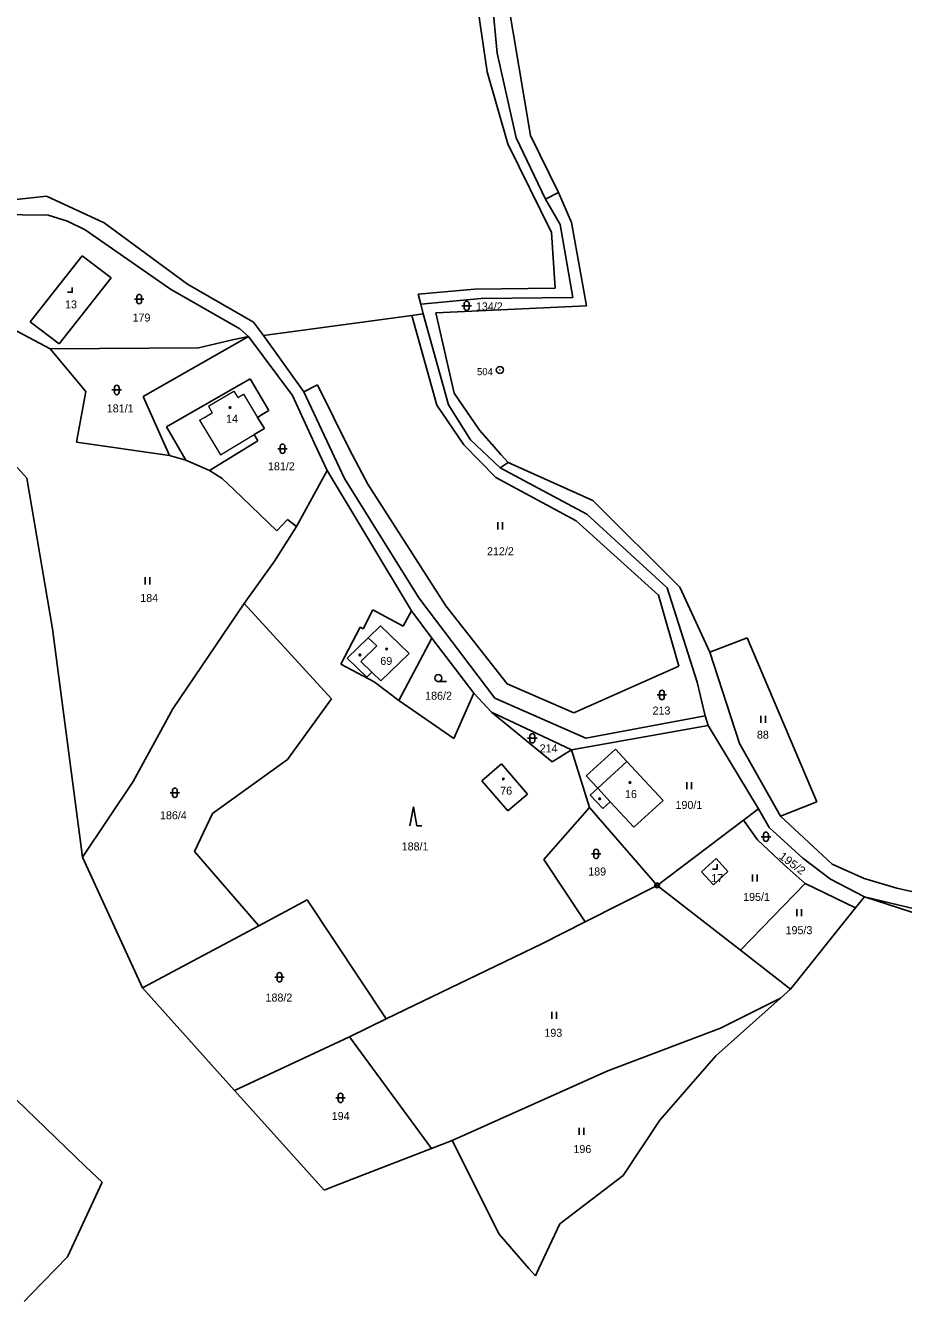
# Model space of a CAD drawing. Extents: x -744132 to -742433, y -984679 to -982287.
# Drawn here: x -742991 to -742804.5, y -984511 to -984240 of the extents above; entities that cross this region are included whole.
import ezdxf
from ezdxf.enums import TextEntityAlignment as Align

# ---------------------------------------------------------------- set-up
doc = ezdxf.new("R2010")
doc.units = 0
doc.header["$LTSCALE"] = 0.68
for name, color, linetype, lineweight in [('1', 7, 'Continuous', 25), ('3', 7, 'Continuous', 25), ('4', 7, 'Continuous', 13), ('5', 7, 'Continuous', 25), ('8', 7, 'Continuous', 25)]:
    doc.layers.add(name, color=color, linetype=linetype, lineweight=lineweight)
doc.layers.add('2', color=7, linetype='Continuous')

msp = doc.modelspace()

# ---------------------------------------------------------------- linework, layer by layer
at = {"layer": '1'}
for p, q in [((-742892.96, -984249.85), (-742897.56, -984218.2)), ((-742893.47, -984218.33), (-742890.83, -984245.87)), ((-742890.85, -984221.06), (-742883.73, -984263.4)), ((-742890.83, -984245.87), (-742886.76, -984263.88)), ((-742888.54, -984265.18), (-742892.96, -984249.85)), ((-742879.29, -984283.96), (-742888.54, -984265.18)), ((-742886.76, -984263.88), (-742880.58, -984276.92)), ((-742996.15, -984277.35), (-742986.54, -984276.26)), ((-742986.54, -984276.26), (-742974.27, -984281.97)), ((-742880.58, -984276.92), (-742877.81, -984275.46)), ((-742880.58, -984276.92), (-742877.42, -984282.31)), ((-742998.92, -984280.13), (-742986.17, -984280.32)), ((-742986.17, -984280.32), (-742982.09, -984281.55)), ((-742982.09, -984281.55), (-742978.35, -984283.42)), ((-742978.35, -984283.42), (-742960.2, -984296.05)), ((-742974.27, -984281.97), (-742956.59, -984294.93)), ((-742878.5, -984295.83), (-742879.29, -984283.96)), ((-742877.42, -984282.31), (-742874.73, -984297.82)), ((-742874.99, -984281.86), (-742871.87, -984299.55)), ((-742978.94, -984288.95), (-742990, -984302.96)), ((-742978.94, -984288.95), (-742972.79, -984293.61)), ((-742972.79, -984293.61), (-742983.86, -984307.62)), ((-742956.59, -984294.93), (-742942.55, -984303.04)), ((-742960.2, -984296.05), (-742945.46, -984304.44)), ((-742907.61, -984297.1), (-742895.64, -984296.05)), ((-742907.03, -984299.2), (-742907.61, -984297.1)), ((-742895.64, -984296.05), (-742878.5, -984295.83)), ((-742874.73, -984297.82), (-742894.23, -984297.98)), ((-743003.32, -984299.32), (-742985.75, -984308.73)), ((-742894.23, -984297.98), (-742907.03, -984299.2)), ((-742906.51, -984301.27), (-742907.03, -984299.2)), ((-742871.87, -984299.55), (-742903.81, -984301.06)), ((-742990, -984302.96), (-742983.86, -984307.62)), ((-742942.55, -984303.04), (-742940.47, -984305.89)), ((-742908.92, -984301.64), (-742940.47, -984305.89)), ((-742906.51, -984301.27), (-742908.92, -984301.64)), ((-742903.6, -984320.66), (-742908.92, -984301.64)), ((-742901.12, -984320.61), (-742906.51, -984301.27)), ((-742903.81, -984301.06), (-742899.93, -984318.14)), ((-742945.46, -984304.44), (-742943.64, -984306.1)), ((-742940.47, -984305.89), (-742931.86, -984317.8)), ((-742985.75, -984308.73), (-742954.24, -984308.5)), ((-742978.18, -984317.77), (-742985.75, -984308.73)), ((-742943.64, -984306.1), (-742965.99, -984318.79)), ((-742954.24, -984308.5), (-742947.02, -984306.78)), ((-742947.02, -984306.78), (-742943.64, -984306.1)), ((-742943.64, -984306.1), (-742934.31, -984318.58)), ((-743012.53, -984312.09), (-742990.72, -984336.15)), ((-742961.06, -984325.25), (-742943.3, -984315.08)), ((-742943.3, -984315.08), (-742939.29, -984321.78)), ((-742931.86, -984317.8), (-742929, -984316.31)), ((-742929, -984316.31), (-742922.17, -984330.04)), ((-742980.17, -984328.49), (-742978.18, -984317.77)), ((-742965.99, -984318.79), (-742960.41, -984331.35)), ((-742934.31, -984318.58), (-742929.6, -984328.78)), ((-742931.86, -984317.8), (-742923.25, -984336.22)), ((-742899.93, -984318.14), (-742894.59, -984325.96)), ((-742940.7, -984322.66), (-742939.29, -984321.78)), ((-742897.88, -984329.09), (-742903.6, -984320.66)), ((-742896.46, -984327.99), (-742901.12, -984320.61)), ((-742941.72, -984323.27), (-742940.7, -984322.66)), ((-742941.72, -984323.27), (-742940.23, -984325.59)), ((-742961.06, -984325.25), (-742956.91, -984332.36)), ((-742942.43, -984326.91), (-742940.23, -984325.59)), ((-742942.43, -984326.91), (-742941.65, -984328.21)), ((-742894.59, -984325.96), (-742889.95, -984331.23)), ((-742980.17, -984328.49), (-742960.41, -984331.35)), ((-742951.92, -984334.5), (-742941.65, -984328.21)), ((-742929.6, -984328.78), (-742926.93, -984334.52)), ((-742922.17, -984330.04), (-742918.26, -984337.45)), ((-742891.12, -984336.05), (-742897.88, -984329.09)), ((-742890.17, -984334), (-742896.46, -984327.99)), ((-742960.41, -984331.35), (-742956.91, -984332.36)), ((-742956.91, -984332.36), (-742951.92, -984334.5)), ((-742888.47, -984332.83), (-742890.17, -984334)), ((-742889.95, -984331.23), (-742888.47, -984332.83)), ((-742888.47, -984332.83), (-742870.47, -984340.88)), ((-742951.92, -984334.5), (-742949.22, -984336.2)), ((-742926.93, -984334.52), (-742933.4, -984346.44)), ((-742926.93, -984334.52), (-742909.03, -984364.31)), ((-742871.79, -984343.84), (-742890.17, -984334)), ((-742985.27, -984368.18), (-742990.72, -984336.15)), ((-742949.22, -984336.2), (-742946.64, -984338.65)), ((-742923.25, -984336.22), (-742907.48, -984361.55)), ((-742918.26, -984337.45), (-742901.68, -984363.3)), ((-742874, -984345.25), (-742891.12, -984336.05)), ((-742946.64, -984338.65), (-742937.6, -984347.37)), ((-742870.47, -984340.88), (-742852, -984359.29)), ((-742854.72, -984359.44), (-742871.79, -984343.84)), ((-742933.4, -984346.44), (-742938.11, -984353.78)), ((-742937.6, -984347.37), (-742935.32, -984344.93)), ((-742935.32, -984344.93), (-742933.4, -984346.44)), ((-742856.52, -984361.01), (-742874, -984345.25)), ((-742938.11, -984353.78), (-742944.56, -984362.78)), ((-742848.31, -984379.52), (-742854.72, -984359.44)), ((-742852, -984359.29), (-742845.66, -984373.09)), ((-742959.7, -984385.15), (-742944.56, -984362.78)), ((-742944.56, -984362.78), (-742925.99, -984383.02)), ((-742907.48, -984361.55), (-742891.34, -984382.9)), ((-742852.21, -984376.09), (-742856.52, -984361.01)), ((-742917.19, -984364.15), (-742919.28, -984368.14)), ((-742910.75, -984367.6), (-742917.19, -984364.15)), ((-742909.03, -984364.31), (-742910.75, -984367.6)), ((-742909.03, -984364.31), (-742904.72, -984370.15)), ((-742901.68, -984363.3), (-742888.67, -984379.86)), ((-742985.27, -984368.18), (-742984.27, -984375.74)), ((-742919.91, -984367.78), (-742924.04, -984375.66)), ((-742919.91, -984367.78), (-742919.28, -984368.14)), ((-742904.72, -984370.15), (-742911.69, -984383.37)), ((-742904.72, -984370.15), (-742895.78, -984381.85)), ((-742845.66, -984373.09), (-742837.75, -984370.04)), ((-742837.75, -984370.04), (-742822.93, -984404.9)), ((-742845.66, -984373.09), (-742839.37, -984392.53)), ((-742984.27, -984375.74), (-742978.89, -984416.62)), ((-742916.96, -984379.45), (-742924.04, -984375.66)), ((-742874.56, -984386.02), (-742852.21, -984376.09)), ((-742916.96, -984379.45), (-742911.69, -984383.37)), ((-742895.78, -984381.85), (-742900.02, -984391.45)), ((-742895.78, -984381.85), (-742892.04, -984385.87)), ((-742888.67, -984379.86), (-742874.56, -984386.02)), ((-742846.63, -984386.61), (-742848.31, -984379.52)), ((-742925.99, -984383.02), (-742935.32, -984395.9)), ((-742911.69, -984383.37), (-742900.02, -984391.45)), ((-742891.34, -984382.9), (-742871.98, -984391.41)), ((-742968.11, -984400.58), (-742959.7, -984385.15)), ((-742892.04, -984385.87), (-742875.01, -984393.85)), ((-742892.04, -984385.87), (-742879.12, -984396.43)), ((-742871.98, -984391.41), (-742846.63, -984386.61)), ((-742846.63, -984386.61), (-742845.98, -984388.72)), ((-742875.01, -984393.85), (-742845.98, -984388.72)), ((-742845.98, -984388.72), (-742835.29, -984406.39)), ((-742839.37, -984392.53), (-742830.66, -984407.93)), ((-742875.01, -984393.85), (-742879.12, -984396.43)), ((-742875.01, -984393.85), (-742871.2, -984406.09)), ((-742865.68, -984393.71), (-742871.91, -984399.38)), ((-742865.68, -984393.71), (-742863.25, -984396.33)), ((-742935.32, -984395.9), (-742951.27, -984407.41)), ((-742889.9, -984396.86), (-742894.07, -984400.45)), ((-742889.9, -984396.86), (-742884.4, -984403.25)), ((-742863.25, -984396.33), (-742855.57, -984404.61)), ((-742978.89, -984416.62), (-742968.11, -984400.58)), ((-742894.07, -984400.45), (-742888.57, -984406.84)), ((-742871.91, -984399.38), (-742869.46, -984402.02)), ((-742884.4, -984403.25), (-742888.57, -984406.84)), ((-742869.46, -984402.02), (-742871.04, -984403.47)), ((-742871.04, -984403.47), (-742868.37, -984406.34)), ((-742871.2, -984406.09), (-742880.93, -984417.12)), ((-742871.2, -984406.09), (-742856.85, -984422.64)), ((-742866.79, -984404.9), (-742868.37, -984406.34)), ((-742866.79, -984404.9), (-742861.8, -984410.28)), ((-742855.57, -984404.61), (-742861.8, -984410.28)), ((-742822.93, -984404.9), (-742830.66, -984407.93)), ((-742951.27, -984407.41), (-742955.12, -984415.43)), ((-742838.51, -984408.81), (-742856.85, -984422.64)), ((-742835.29, -984406.39), (-742838.51, -984408.81)), ((-742838.51, -984408.81), (-742835.49, -984412.96)), ((-742835.29, -984406.39), (-742833.01, -984410.37)), ((-742830.66, -984407.93), (-742819.67, -984418.14)), ((-742833.01, -984410.37), (-742825.86, -984416.85)), ((-742835.49, -984412.96), (-742829.88, -984418.31)), ((-742978.89, -984416.62), (-742966.17, -984444.4)), ((-742955.12, -984415.43), (-742941.41, -984431.2)), ((-742880.93, -984417.12), (-742872.12, -984430.39)), ((-742844.33, -984416.91), (-742847.42, -984419.77)), ((-742844.33, -984416.91), (-742841.8, -984419.66)), ((-742825.86, -984416.85), (-742820.01, -984421.35)), ((-742847.42, -984419.77), (-742844.89, -984422.51)), ((-742841.8, -984419.66), (-742844.89, -984422.51)), ((-742829.88, -984418.31), (-742825.4, -984422.23)), ((-742819.67, -984418.14), (-742812.88, -984421.17)), ((-742825.4, -984422.23), (-742814.7, -984427.44)), ((-742820.01, -984421.35), (-742812.82, -984425.09)), ((-742812.88, -984421.17), (-742805.92, -984423.24)), ((-742872.12, -984430.39), (-742856.85, -984422.64)), ((-742856.85, -984422.64), (-742839.15, -984436.38)), ((-742814.7, -984427.44), (-742812.82, -984425.09)), ((-742812.82, -984425.09), (-742756.42, -984443.42)), ((-742812.82, -984425.09), (-742792.97, -984429.85)), ((-742805.92, -984423.24), (-742773.27, -984430.71)), ((-742941.41, -984431.2), (-742931.14, -984425.72)), ((-742931.14, -984425.72), (-742914.38, -984451)), ((-742828.48, -984444.67), (-742814.7, -984427.44)), ((-742881.31, -984435.05), (-742872.12, -984430.39)), ((-742966.17, -984444.4), (-742941.41, -984431.2)), ((-742914.38, -984451), (-742881.31, -984435.05)), ((-742966.17, -984444.4), (-742946.58, -984466.2)), ((-742843.39, -984452.96), (-742830.65, -984446.61)), ((-742830.65, -984446.61), (-742828.48, -984444.67)), ((-742922.21, -984454.78), (-742914.38, -984451)), ((-742946.58, -984466.2), (-742922.21, -984454.78)), ((-742922.21, -984454.78), (-742904.79, -984478.55)), ((-742867.31, -984462.05), (-742843.39, -984452.96)), ((-742900.37, -984476.84), (-742867.31, -984462.05)), ((-742978.22, -984482.31), (-742992.99, -984468.09)), ((-742946.58, -984466.2), (-742942.07, -984471.22)), ((-742942.07, -984471.22), (-742927.56, -984487.36)), ((-742864.07, -984484.25), (-742856.23, -984472.49)), ((-742921.61, -984485.06), (-742904.79, -984478.55)), ((-742904.79, -984478.55), (-742900.37, -984476.84)), ((-742900.37, -984476.84), (-742890.41, -984496.74)), ((-742974.73, -984485.67), (-742978.22, -984482.31)), ((-742877.53, -984494.51), (-742864.07, -984484.25)), ((-742982.08, -984501.56), (-742974.73, -984485.67)), ((-742927.56, -984487.36), (-742925.41, -984486.53)), ((-742925.41, -984486.53), (-742921.61, -984485.06)), ((-742882.01, -984504.14), (-742877.53, -984494.51)), ((-742884.09, -984503.98), (-742890.41, -984496.74)), ((-742989.77, -984509.49), (-742982.08, -984501.56)), ((-742882.68, -984505.59), (-742884.09, -984503.98)), ((-742882.68, -984505.59), (-742882.01, -984504.14)), ((-742991.25, -984511.01), (-742989.77, -984509.49))]:
    msp.add_line(p, q, dxfattribs=at)
for points in [[(-742883.73, -984263.4), (-742877.81, -984275.46), (-742874.99, -984281.86)], [(-742825.4, -984422.23), (-742839.15, -984436.38), (-742828.48, -984444.67)], [(-742856.23, -984472.49), (-742844.37, -984458.87), (-742830.65, -984446.61)]]:
    msp.add_lwpolyline(points, dxfattribs=at)
at = {"layer": '3'}
for p, q in [((-742967.341, -984297.631), (-742967.341, -984298.632)), ((-742966.339, -984298.632), (-742966.339, -984297.631)), ((-742967.841, -984298.131), (-742965.839, -984298.131)), ((-742898.291, -984299.551), (-742896.289, -984299.551)), ((-742897.791, -984299.051), (-742897.791, -984300.052)), ((-742896.789, -984300.052), (-742896.789, -984299.051)), ((-742972.621, -984317.431), (-742970.619, -984317.431)), ((-742972.121, -984316.931), (-742972.121, -984317.932)), ((-742971.119, -984317.932), (-742971.119, -984316.931)), ((-742937.391, -984329.921), (-742935.389, -984329.921)), ((-742936.891, -984329.421), (-742936.891, -984330.422)), ((-742935.889, -984330.422), (-742935.889, -984329.421)), ((-742890.691, -984347.04), (-742890.691, -984345.54)), ((-742889.69, -984347.04), (-742889.69, -984345.54)), ((-742965.571, -984358.72), (-742965.571, -984357.22)), ((-742964.57, -984358.72), (-742964.57, -984357.22)), ((-742903.323, -984379.37), (-742901.573, -984379.37)), ((-742856.321, -984381.711), (-742856.321, -984382.712)), ((-742855.319, -984382.712), (-742855.319, -984381.711)), ((-742856.821, -984382.211), (-742854.819, -984382.211)), ((-742834.831, -984388.12), (-742834.831, -984386.62)), ((-742833.83, -984388.12), (-742833.83, -984386.62)), ((-742884.341, -984391.401), (-742882.339, -984391.401)), ((-742883.841, -984390.901), (-742883.841, -984391.902)), ((-742882.839, -984391.902), (-742882.839, -984390.901)), ((-742850.541, -984402.23), (-742850.541, -984400.73)), ((-742849.54, -984402.23), (-742849.54, -984400.73)), ((-742960.261, -984402.981), (-742958.259, -984402.981)), ((-742959.761, -984402.481), (-742959.761, -984403.482)), ((-742958.759, -984403.482), (-742958.759, -984402.481)), ((-742907.84, -984409.97), (-742906.844, -984409.97)), ((-742834.721, -984412.311), (-742832.719, -984412.311)), ((-742834.221, -984411.811), (-742834.221, -984412.812)), ((-742833.219, -984412.812), (-742833.219, -984411.811)), ((-742870.801, -984415.951), (-742868.799, -984415.951)), ((-742870.301, -984415.451), (-742870.301, -984416.452)), ((-742869.299, -984416.452), (-742869.299, -984415.451)), ((-742836.601, -984421.85), (-742836.601, -984420.35)), ((-742835.6, -984421.85), (-742835.6, -984420.35)), ((-742827.201, -984429.16), (-742827.201, -984427.66)), ((-742826.2, -984429.16), (-742826.2, -984427.66)), ((-742938.051, -984442.151), (-742936.049, -984442.151)), ((-742937.551, -984441.651), (-742937.551, -984442.652)), ((-742936.549, -984442.652), (-742936.549, -984441.651)), ((-742879.201, -984450.98), (-742879.201, -984449.48)), ((-742878.2, -984450.98), (-742878.2, -984449.48)), ((-742925.081, -984467.781), (-742923.079, -984467.781)), ((-742924.581, -984467.281), (-742924.581, -984468.282)), ((-742923.579, -984468.282), (-742923.579, -984467.281)), ((-742873.411, -984475.64), (-742873.411, -984474.14)), ((-742872.41, -984475.64), (-742872.41, -984474.14))]:
    msp.add_line(p, q, dxfattribs=at)
for points in [[(-742982.061, -984296.68), (-742981.06, -984296.68), (-742981.06, -984295.68)], [(-742907.84, -984409.97), (-742908.59, -984405.97), (-742909.34, -984409.97)], [(-742845.101, -984419.17), (-742844.1, -984419.17), (-742844.1, -984418.17)]]:
    msp.add_lwpolyline(points, dxfattribs=at)
msp.add_circle((-742903.3229, -984378.6198), 0.75, dxfattribs=at)
for centre, start, end in [((-742966.84, -984297.6309), 0, 180), ((-742966.84, -984298.6309), 180, 359.98789), ((-742897.29, -984299.0509), 0, 180), ((-742897.29, -984300.0509), 180, 359.98789), ((-742971.62, -984316.9309), 0, 180), ((-742971.62, -984317.9309), 180, 359.98789), ((-742936.39, -984329.4209), 0, 180), ((-742936.39, -984330.4209), 180, 359.98789), ((-742855.82, -984381.7109), 0, 180), ((-742855.82, -984382.7109), 180, 359.98789), ((-742883.34, -984390.9009), 0, 180), ((-742883.34, -984391.9009), 180, 359.98789), ((-742959.26, -984402.4809), 0, 180), ((-742959.26, -984403.4809), 180, 359.98789), ((-742833.72, -984411.8109), 0, 180), ((-742833.72, -984412.8109), 180, 359.98789), ((-742869.8, -984415.4509), 0, 180), ((-742869.8, -984416.4509), 180, 359.98789), ((-742937.05, -984441.6509), 0, 180), ((-742937.05, -984442.6509), 180, 359.98789), ((-742924.08, -984467.2809), 0, 180), ((-742924.08, -984468.2809), 180, 359.98789)]:
    msp.add_arc(centre, 0.5, start, end, dxfattribs=at)
at = {"layer": '4'}
for p, q in [((-742951.53, -984320.54), (-742946.73, -984317.67)), ((-742946.73, -984317.67), (-742945.91, -984319.04)), ((-742945.91, -984319.04), (-742944.69, -984318.31)), ((-742944.69, -984318.31), (-742941.72, -984323.27)), ((-742953.11, -984323.35), (-742951.31, -984322.28)), ((-742952.12, -984320.89), (-742951.53, -984320.54)), ((-742952.12, -984320.89), (-742951.31, -984322.28)), ((-742954, -984323.88), (-742953.11, -984323.35)), ((-742954, -984323.88), (-742949.6, -984331.18)), ((-742949.6, -984331.18), (-742942.43, -984326.91)), ((-742915.59, -984367.54), (-742918.2, -984370.05)), ((-742915.59, -984367.54), (-742909.52, -984373.39)), ((-742918.2, -984370.05), (-742922.69, -984374.37)), ((-742909.52, -984373.39), (-742915.54, -984379.19)), ((-742922.69, -984374.37), (-742918.49, -984378.41)), ((-742919.8, -984375.09), (-742917.4, -984377.39)), ((-742918.49, -984378.41), (-742917.4, -984377.39)), ((-742917.4, -984377.39), (-742915.54, -984379.19)), ((-742863.25, -984396.33), (-742869.46, -984402.02)), ((-742869.46, -984402.02), (-742866.79, -984404.9))]:
    msp.add_line(p, q, dxfattribs=at)
msp.add_lwpolyline([(-742918.2, -984370.05), (-742916.38, -984371.8), (-742919.8, -984375.09)], dxfattribs=at)
at = {"layer": '5'}
for centre in [(-742947.5468, -984321.1592), (-742919.9668, -984373.6892), (-742914.2868, -984372.4592), (-742889.4968, -984400.0592), (-742862.5868, -984400.7992), (-742869.0568, -984404.2592)]:
    msp.add_circle(centre, 0.175, dxfattribs=at)
at = {"layer": '8'}
for centre, radius in [((-742890.24, -984313.1798), 0.75), ((-742890.24, -984313.1798), 0.03), ((-742856.85, -984422.6399), 0.5), ((-742856.85, -984422.6399), 0.0303)]:
    msp.add_circle(centre, radius, dxfattribs=at)

# ---------------------------------------------------------------- texts
at = {"layer": '2'}
for s, p in [('13', (-742982.58, -984300.105)), ('134/2', (-742895.33, -984300.535)), ('179', (-742968.25, -984302.905)), ('181/1', (-742973.72, -984322.195)), ('14', (-742948.4, -984324.385)), ('181/2', (-742939.49, -984334.495)), ('212/2', (-742892.97, -984352.535)), ('184', (-742966.61, -984362.455)), ('69', (-742915.63, -984375.825)), ('186/2', (-742906.11, -984383.215)), ('213', (-742857.81, -984386.365)), ('88', (-742835.64, -984391.495)), ('214', (-742881.79, -984394.395)), ('76', (-742890.16, -984403.375)), ('16', (-742863.66, -984404.105)), ('190/1', (-742852.93, -984406.405)), ('186/4', (-742962.42, -984408.615)), ('188/1', (-742911.09, -984415.225)), ('189', (-742871.47, -984420.545)), ('17', (-742845.35, -984421.955)), ('195/1', (-742838.57, -984425.935)), ('195/3', (-742829.56, -984433.005)), ('188/2', (-742940.01, -984447.315)), ('193', (-742880.78, -984454.795)), ('194', (-742925.95, -984472.475)), ('196', (-742874.61, -984479.485))]:
    msp.add_text(s, height=1.7, dxfattribs=at).set_placement(p)
at = {"layer": '2', "width": 1.1}
msp.add_text('195/2', height=1.7, rotation=323, dxfattribs=at).set_placement((-742831.125, -984416.759))
at = {"layer": '8'}
msp.add_text('504', height=1.5, dxfattribs=at).set_placement((-742891.739, -984314.297), align=Align.RIGHT)

doc.saveas('drawing.dxf')
